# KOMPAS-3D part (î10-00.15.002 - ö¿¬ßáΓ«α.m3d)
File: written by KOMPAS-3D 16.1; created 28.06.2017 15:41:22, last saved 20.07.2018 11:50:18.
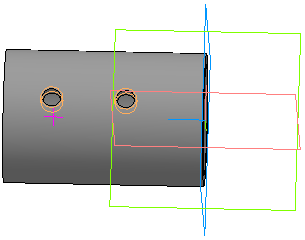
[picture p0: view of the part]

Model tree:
1. Эскиз:1
2. Операция выдавливания:1
     Расстояние 1 = 54
3. Фаска:1
     Угол = 45; Длина 1 = 1; Длина 2 = 1
4. Эскиз:2
5. Отверстие:1
     Глубина выреза = 18; Диаметр отверстия = 4.91747; Угол конуса торца = 118; Координата Y = -41
6. M6
     Длина резьбы = 18; Шаг резьбы = 1; Номинальный диаметр резьбы = 6
7. Массив по сетке:1  (with: Отверстие:1, Эскиз:2)  (2 pattern instances)

Referenced files in C:\Program Files\ASCON\KOMPAS-3D V16\Sys\Thread\: cil0_8724-2002 coarse.xml
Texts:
  Шаг 1
  Режим 1
  Направление 1
  Шаг 2
  Режим 2
  Направление 2
  Номер 1
  Номер 2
